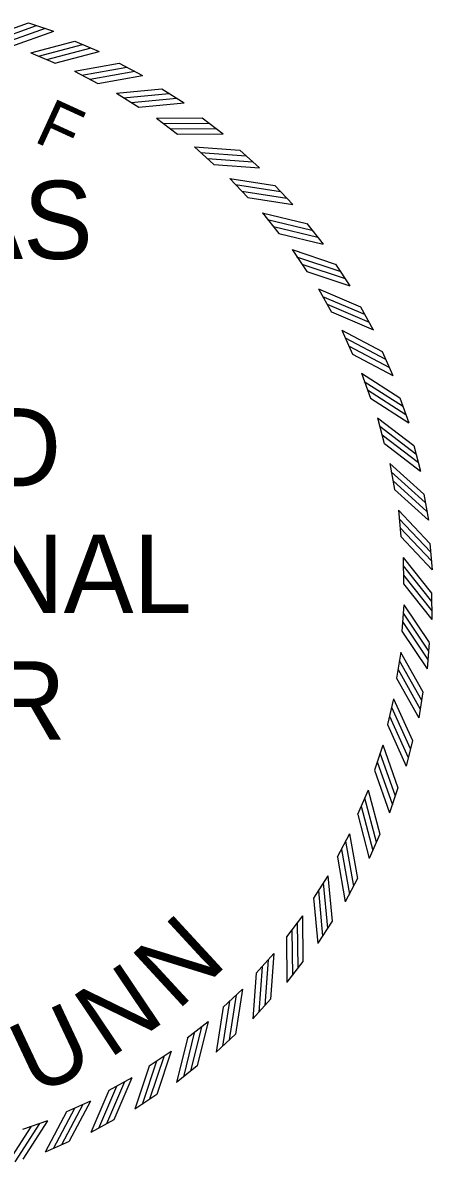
# Model space of a CAD drawing. Extents: x -43543 to 34500, y -13675 to 11152.
# Drawn here: x 10683 to 11529, y -8493 to -6130 of the extents above; entities that cross this region are included whole.
import ezdxf

# ---------------------------------------------------------------- set-up
doc = ezdxf.new("R2010")
doc.units = 0
doc.layers.add('STAMP', color=7, linetype='Continuous')

msp = doc.modelspace()

# ---------------------------------------------------------------- linework, layer by layer
at = {"layer": 'STAMP'}
for p, q in [((10694.9, -6130.2), (10746.6, -6147.4)), ((10790.4, -6168), (10840.5, -6189.5)), ((10699.2, -6192.1), (10749.5, -6213.6)), ((10882.4, -6213.6), (10930.6, -6239.1)), ((10789.6, -6230.1), (10837.9, -6255.6)), ((10876.5, -6275.4), (10922.5, -6304.8)), ((10970.4, -6266.6), (11016.3, -6296)), ((10959.4, -6327.7), (11002.8, -6360.8)), ((11053.7, -6326.7), (11097, -6359.8)), ((11037.7, -6386.7), (11078.2, -6423.3)), ((11131.7, -6393.5), (11172.2, -6430.1)), ((11110.8, -6451.9), (11148.2, -6491.8)), ((11204, -6466.5), (11241.2, -6506.3)), ((11178.3, -6523), (11212.3, -6565.8)), ((11270, -6545.2), (11303.8, -6587.9)), ((11239.7, -6599.4), (11270, -6644.8)), ((11329.2, -6629.1), (11359.4, -6674.5)), ((11294.6, -6680.6), (11321, -6728.4)), ((11381.3, -6717.6), (11407.7, -6765.3)), ((11342.6, -6766.1), (11365, -6815.9)), ((11426, -6810.1), (11448.3, -6859.8)), ((11383.4, -6855.2), (11401.6, -6906.7)), ((11462.8, -6906), (11481, -6957.4)), ((11416.6, -6947.4), (11430.5, -7000.2)), ((11491.6, -7004.6), (11505.5, -7057.3)), ((11442.2, -7042), (11451.7, -7095.8)), ((11512.2, -7105.2), (11521.6, -7158.9)), ((11459.8, -7138.5), (11464.8, -7192.8)), ((11524.4, -7207.2), (11529.4, -7261.4)), ((11469.4, -7236), (11469.9, -7290.6)), ((11528.1, -7309.8), (11528.6, -7364.3)), ((11471, -7334), (11466.9, -7388.5)), ((11523.3, -7412.4), (11519.3, -7466.8)), ((11464.4, -7431.8), (11455.9, -7485.7)), ((11510.1, -7514.3), (11501.6, -7568.1)), ((11449.8, -7528.7), (11436.8, -7581.8)), ((11427.2, -7624.1), (11409.9, -7675.9)), ((11488.5, -7614.7), (11475.6, -7667.6)), ((11396.8, -7717.3), (11375.3, -7767.5)), ((11458.7, -7713), (11441.5, -7764.7)), ((11358.8, -7807.7), (11333.3, -7855.9)), ((11420.9, -7808.5), (11399.5, -7858.6)), ((11313.5, -7894.6), (11284.1, -7940.6)), ((11375.3, -7900.5), (11349.8, -7948.6)), ((11261.2, -7977.5), (11228.1, -8020.9)), ((11322.3, -7988.5), (11292.9, -8034.3)), ((11202.2, -8055.7), (11165.6, -8096.3)), ((11262.2, -8071.7), (11229.1, -8115)), ((11137, -8128.9), (11097.1, -8166.2)), ((11195.4, -8149.8), (11158.9, -8190.2)), ((11065.9, -8196.4), (11023.1, -8230.3)), ((11122.4, -8222), (11082.7, -8259.3)), ((10989.5, -8257.8), (10944.1, -8288.1)), ((11043.7, -8288), (11001, -8321.9)), ((10908.3, -8312.7), (10860.5, -8339.1)), ((10822.8, -8360.6), (10773, -8383)), ((10959.8, -8347.3), (10914.5, -8377.5)), ((10733.7, -8401.4), (10682.2, -8419.6)), ((10871.3, -8399.4), (10823.6, -8425.8)), ((10778.8, -8444), (10729.1, -8466.4))]:
    msp.add_line(p, q, dxfattribs=at)
for points in [[(10606, -6161.8), (10694.8, -6130.2)], [(10622.6, -6167.4), (10711.4, -6135.9)], [(10640.7, -6173), (10729.5, -6141.5)], [(10657.8, -6178.9), (10746.7, -6147.4)], [(10699.2, -6192.1), (10790.3, -6168)], [(10715.2, -6199.2), (10806.4, -6175.1)], [(10732.8, -6206.2), (10823.9, -6182.2)], [(10749.4, -6213.5), (10840.6, -6189.4)], [(10789.5, -6230.1), (10882.4, -6213.6)], [(10805, -6238.4), (10897.8, -6222)], [(10821.9, -6246.9), (10914.7, -6230.4)], [(10837.8, -6255.6), (10930.7, -6239.1)], [(10876.4, -6275.4), (10970.3, -6266.6)], [(10891.1, -6285), (10985, -6276.2)], [(10907.3, -6294.8), (11001.2, -6286.1)], [(10922.5, -6304.7), (11016.4, -6296)], [(10959.3, -6327.7), (11053.6, -6326.7)], [(10973.2, -6338.5), (11067.4, -6337.5)], [(10988.5, -6349.6), (11082.7, -6348.7)], [(11002.8, -6360.8), (11097.1, -6359.8)], [(11037.6, -6386.7), (11131.6, -6393.5)], [(11050.5, -6398.6), (11144.5, -6405.4)], [(11064.8, -6410.9), (11158.9, -6417.8)], [(11078.2, -6423.2), (11172.2, -6430.1)], [(11110.7, -6451.9), (11203.9, -6466.5)], [(11122.6, -6464.8), (11215.8, -6479.4)], [(11135.9, -6478.3), (11229, -6492.9)], [(11148.2, -6491.7), (11241.3, -6506.3)], [(11178.2, -6523), (11269.9, -6545.2)], [(11189, -6536.8), (11280.6, -6559)], [(11201.1, -6551.4), (11292.7, -6573.6)], [(11212.3, -6565.7), (11303.9, -6587.9)], [(11239.7, -6599.4), (11329.1, -6629.1)], [(11249.2, -6614.1), (11338.7, -6643.8)], [(11260.1, -6629.6), (11349.6, -6659.3)], [(11270, -6644.8), (11359.5, -6674.5)], [(11294.5, -6680.6), (11381.3, -6717.6)], [(11302.9, -6696), (11389.6, -6733)], [(11312.4, -6712.4), (11399.1, -6749.4)], [(11321, -6728.3), (11407.8, -6765.3)], [(11342.5, -6766), (11425.9, -6810.1)], [(11349.6, -6782.1), (11432.9, -6826.1)], [(11357.7, -6799.2), (11441.1, -6843.2)], [(11365, -6815.8), (11448.4, -6859.8)], [(11383.3, -6855.2), (11462.7, -6905.9)], [(11389, -6871.8), (11468.4, -6922.5)], [(11395.7, -6889.5), (11475.1, -6940.2)], [(11401.6, -6906.6), (11481, -6957.4)], [(11416.6, -6947.4), (11491.6, -7004.5)], [(11420.9, -6964.4), (11495.9, -7021.5)], [(11426.1, -6982.6), (11501.1, -7039.7)], [(11430.6, -7000.2), (11505.5, -7057.3)], [(11442.1, -7042), (11512.1, -7105.1)], [(11445, -7059.3), (11515, -7122.4)], [(11448.7, -7077.9), (11518.7, -7141)], [(11451.7, -7095.8), (11521.7, -7158.9)], [(11459.8, -7138.4), (11524.3, -7207.1)], [(11461.2, -7155.9), (11525.8, -7224.6)], [(11463.4, -7174.7), (11527.9, -7243.4)], [(11464.9, -7192.8), (11529.4, -7261.5)], [(11469.4, -7235.9), (11528, -7309.7)], [(11469.4, -7253.5), (11528, -7327.3)], [(11470, -7272.4), (11528.6, -7346.2)], [(11470, -7290.5), (11528.6, -7364.4)], [(11470.9, -7333.9), (11523.3, -7412.3)], [(11468.5, -7370.3), (11520.9, -7448.7)], [(11469.5, -7351.4), (11521.8, -7429.8)], [(11467, -7388.4), (11519.4, -7466.8)], [(11464.3, -7431.7), (11510.1, -7514.2)], [(11461.5, -7449), (11507.2, -7531.5)], [(11455.9, -7485.7), (11501.7, -7568.1)], [(11458.9, -7467.8), (11504.6, -7550.2)], [(11449.7, -7528.6), (11488.5, -7614.6)], [(11445.4, -7545.6), (11484.2, -7631.6)], [(11436.9, -7581.7), (11475.6, -7667.7)], [(11441.4, -7564.1), (11480.1, -7650.1)], [(11427.2, -7624), (11458.7, -7712.9)], [(11421.5, -7640.6), (11453, -7729.5)], [(11410, -7675.9), (11441.5, -7764.7)], [(11415.9, -7658.7), (11447.4, -7747.6)], [(11396.8, -7717.2), (11420.9, -7808.4)], [(11389.7, -7733.3), (11413.8, -7824.4)], [(11375.4, -7767.5), (11399.5, -7858.6)], [(11382.7, -7750.8), (11406.8, -7842)], [(11358.8, -7807.6), (11375.3, -7900.4)], [(11342, -7839.9), (11358.5, -7932.7)], [(11350.5, -7823), (11366.9, -7915.8)], [(11333.4, -7855.9), (11349.8, -7948.7)], [(11303.9, -7909.2), (11312.7, -8003)], [(11313.5, -7894.5), (11322.3, -7988.4)], [(11294.1, -7925.3), (11302.8, -8019.2)], [(11284.2, -7940.5), (11292.9, -8034.4)], [(11261.2, -7977.4), (11262.2, -8071.6)], [(11239.3, -8006.5), (11240.3, -8100.8)], [(11250.4, -7991.2), (11251.4, -8085.5)], [(11228.1, -8020.8), (11229.1, -8115.1)], [(11202.2, -8055.7), (11195.4, -8149.7)], [(11190.4, -8068.6), (11183.5, -8162.6)], [(11165.7, -8096.2), (11158.9, -8190.3)], [(11178, -8082.9), (11171.1, -8176.9)], [(11124.1, -8140.7), (11109.5, -8233.8)], [(11137, -8128.8), (11122.4, -8221.9)], [(11097.2, -8166.2), (11082.6, -8259.4)], [(11110.6, -8153.9), (11096, -8247.1)], [(11065.9, -8196.3), (11043.7, -8287.9)], [(11037.5, -8219.2), (11015.3, -8310.8)], [(11052.1, -8207.1), (11029.9, -8298.7)], [(11023.2, -8230.3), (11001, -8321.9)], [(10974.9, -8267.3), (10945.1, -8356.8)], [(10989.5, -8257.7), (10959.8, -8347.2)], [(10944.1, -8288.1), (10914.4, -8377.5)], [(10959.3, -8278.1), (10929.6, -8367.6)], [(10908.3, -8312.6), (10871.3, -8399.3)], [(10860.6, -8339.1), (10823.6, -8425.8)], [(10876.5, -8330.5), (10839.6, -8417.2)], [(10892.9, -8320.9), (10855.9, -8407.6)], [(10822.9, -8360.6), (10778.8, -8443.9)], [(10773.1, -8383.1), (10729.1, -8466.4)], [(10789.7, -8375.8), (10745.7, -8459.1)], [(10806.8, -8367.6), (10762.8, -8451)], [(10717.2, -8407), (10666.4, -8486.5)], [(10733.7, -8401.3), (10683, -8480.8)], [(10699.4, -8413.7), (10648.7, -8493.2)]]:
    msp.add_lwpolyline(points, dxfattribs=at)

# ---------------------------------------------------------------- texts
for s, height, rotation, p in [('F', 99.1, 335.3628, (10703.1, -6374.7)), ('N', 150.5, 42.6817, (11001.8, -8175.7)), ('N', 150.5, 33.9264, (10860.8, -8274.5)), ('U', 150.5, 25.1712, (10706.4, -8350.7))]:
    msp.add_text(s, height=height, rotation=rotation, dxfattribs=at).set_placement(p)
for s, height, p in [('ARKANSAS', 161.78, (9649.5, -6618.7)), ('LICENSED', 161.78, (9680.3, -7088.9)), ('PROFESSIONAL', 161.779, (9349, -7350.8)), ('ENGINEER', 161.78, (9641.8, -7612.7))]:
    msp.add_text(s, height=height, dxfattribs=at).set_placement(p)

doc.saveas('drawing.dxf')
